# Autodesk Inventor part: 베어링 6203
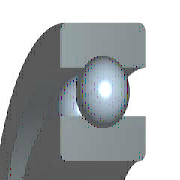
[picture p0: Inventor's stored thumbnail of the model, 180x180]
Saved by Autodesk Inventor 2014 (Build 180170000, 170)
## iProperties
IsCustomPart: 0
Created: 2016-04
Part Number: 베어링 6203
Material: 알루미늄 6061
Description: 깊은 그루브 볼 베어링
Document SubType Name: Modeling
Standard: KS B 2023
Designer: mdu
Standards Organization: KS
Language: ko-KR
Size Designation: 6203 - 17 x 40 x 12
Categories: <MemberInstance><Categories><Category DisplayName="샤프트 부품" InternalName="7f7aeb1f-a693-4053-b835-cee3144e0d98" Mnemonic="SHFT"><Category DisplayName="베어링" Inter
Density: 2.71 g/cm^3
Mass: 22.4044 g
Surface Area: 64.3582 cm^2
Volume: 8.26729 cm^3
Appearance: Aluminum - Flat
Author: mdu
Revision Number: 1
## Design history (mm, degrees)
sketch "스케치" dims "d0" = 5.98 (= -0.26 x WD + 0.26 x BD)
  geometry: L1 (3.01, 14.25)-(8.99, 14.25); L2 (6, 14.25)-(6, 11.26); L3 (6, 14.25)-(6, 17.24); L4 (3.778, 12.249)-(0, 12.249); L5 (0, 8.5)-(12, 8.5); L6 (3.778, 16.251)-(0, 16.251); L7 (0, 20)-(12, 20); L8 (12, 8.5)-(12, 12.249); L9 (8.222, 12.249)-(12, 12.249); L10 (8.222, 16.251)-(12, 16.251); L11 (12, 20)-(12, 16.251); L12 (-1.4, 0)-(8.4, 0) reference; L13 (0, -0.3)-(0, 5.3) reference
  constraints: 22 end point, 4 point on line, 2 collinear, 2 perpendicular, 2 symmetric about line, 1 midpoint, 1 parallel, 14 other
  dimensions: "d9" = 17 diameter of L5 L12 (= WD); "d11" = 40 diameter of L7 L12 (= BD); "d12" = 12 distance between parallel lines of L8 L13 (= KB); "d13" = 24.498 diameter of L9 L12 (= 0.326 x BD + 0.674 x WD)
revolve "본체" stored, may be unused: angle "d6" = 90 deg
revolve "볼" stored, may be unused: angle "d7" = 90 deg
pattern_circular "IDS_ARRAYBALL[SIMPL:T]" dims angle "d3" = 360 deg
body "Solid1"
fillet "모깎기1" dims "d1" = 0.6 (= KRS)
other parameters: "WD" = 17 [user parameter; used in 5 equation terms], "BD" = 40 [user parameter; used in 5 equation terms], "KB" = 12 [user parameter; used in 1 equation term], "KRS" = 0.6 [user parameter; used in 1 equation term], "d4" = 0, "d5" = 0, "d8" = 0, "d14" = 0, "d15" = 0, "BBA" = 0 [user parameter], "BC0" = 4750000 [user parameter], "BC" = 9560000 [user parameter], "WR" = 8.5 (= 0.5 x WD) [user parameter]
